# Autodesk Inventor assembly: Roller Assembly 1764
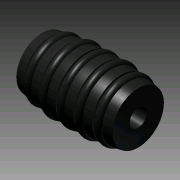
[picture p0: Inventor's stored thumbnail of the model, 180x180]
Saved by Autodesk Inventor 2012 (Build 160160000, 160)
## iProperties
Created: 2007-11
Part Number: Roller Assembly 1764
Document SubType Name: Assembly
Designer: lwoods
Author: lwoods
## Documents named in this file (4)
- R:\CAD Archives\Wheels_1764\Omniwheel_1764\Roller_Assembly_1764.iam
- R:\CAD Archives\Wheels_1764\Omniwheel_1764\Roller_Ridges_1764.ipt
- R:\CAD Archives\Wheels_1764\Omniwheel_1764\O_Ring_1_R.609_1764.ipt
- R:\CAD Archives\Wheels_1764\Omniwheel_1764\O Ring_2_R.671_1764.ipt
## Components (6 placed, 3 different names)
1. Roller_Ridges_1764:1 — Mate:2, Mate:7, Mate:11, Mate:16, Mate:19, Mate:25
2. O_Ring_1_R.609_1764:1 — Mate:4, Angle:1, Mate:6
3. O_Ring_1_R.609_1764:2 — Mate:8, Angle:2, Mate:9
4. O Ring_2_R.671_1764:1 — Mate:13, Angle:3, Mate:14
5. O Ring_2_R.671_1764:2 — Mate:12, Angle:4, Mate:17
6. O Ring_2_R.671_1764:3 — Mate:20, Angle:6, Mate:23
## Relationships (21: Mate 16, Angle 5)
- Mate:2: Roller_Ridges_1764:1
- Mate:4: O_Ring_1_R.609_1764:1
- Angle:1: O_Ring_1_R.609_1764:1
- Mate:6: O_Ring_1_R.609_1764:1
- Mate:7: Roller_Ridges_1764:1
- Mate:8: O_Ring_1_R.609_1764:2
- Angle:2: O_Ring_1_R.609_1764:2
- Mate:9: O_Ring_1_R.609_1764:2
- Mate:11: Roller_Ridges_1764:1
- Mate:12: O Ring_2_R.671_1764:2
- Mate:13: O Ring_2_R.671_1764:1
- Angle:3: O Ring_2_R.671_1764:1
- Mate:14: O Ring_2_R.671_1764:1
- Mate:16: Roller_Ridges_1764:1
- Angle:4: O Ring_2_R.671_1764:2
- Mate:17: O Ring_2_R.671_1764:2
- Mate:19: Roller_Ridges_1764:1
- Mate:20: O Ring_2_R.671_1764:3
- Angle:6: O Ring_2_R.671_1764:3
- Mate:23: O Ring_2_R.671_1764:3
- Mate:25: Roller_Ridges_1764:1
